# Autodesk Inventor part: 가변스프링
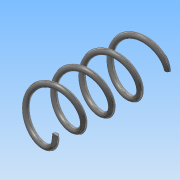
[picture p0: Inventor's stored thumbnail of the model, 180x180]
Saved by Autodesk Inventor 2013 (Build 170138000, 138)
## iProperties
Created: 2015-09
Part Number: 가변스프링
Material: 강철, 탄소
Document SubType Name: Modeling
Designer: Administrator
Density: 7.87 g/cm^3
Mass: 4.92065 g
Surface Area: 12.7467 cm^2
Volume: 0.625242 cm^3
Author: Administrator
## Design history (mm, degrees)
sketch "스케치1"
  geometry: L1 (0, 0)-(0, -42); L2 (0, -42)-(8, -42); L3 (0, 0)-(-8, 0); C1 r 1 at (8, 0)
  constraints: 7 end point, 1 centre point, 1 horizontal alignment, 1 parallel, 1 perpendicular, 1 vertical
  dimensions: "d0" = 42 distance of L1.end L1.start (derived); "d1" = 2 diameter of C1; "d2" = 16 diameter of C1.centre L1; "d3" = 8 distance of L1.start L3.end; "d4" = 8 distance of L1.end L2.end
feature "코일1" sketch "스케치1" pitch "d5" = 10; turns "d7" = 4; dims "d6" = 42 (= d0), "d8" = 0, angle "d9" = 90 deg, angle "d10" = 90 deg, "d11" = 0, "d12" = 0
sketch "스케치2"
  geometry: L1 (-42, 9)-(0, 9); L2 (0, 9)-(0, -9); L3 (0, -9)-(-42, -9); L4 (-42, -9)-(-42, 9); 2 further points
  constraints: 8 end point, 2 parallel, 1 coincident, 1 horizontal, 1 midpoint, 1 perpendicular
  dimensions: "d13" = 18 distance of L3.end L1.start; "d15" = 42 distance of L2.end L3.end (derived)
extrude "돌출1" sketch "스케치2" stored distance "d16" = 0; taper "d17" = 0 deg
node "솔리드1"
